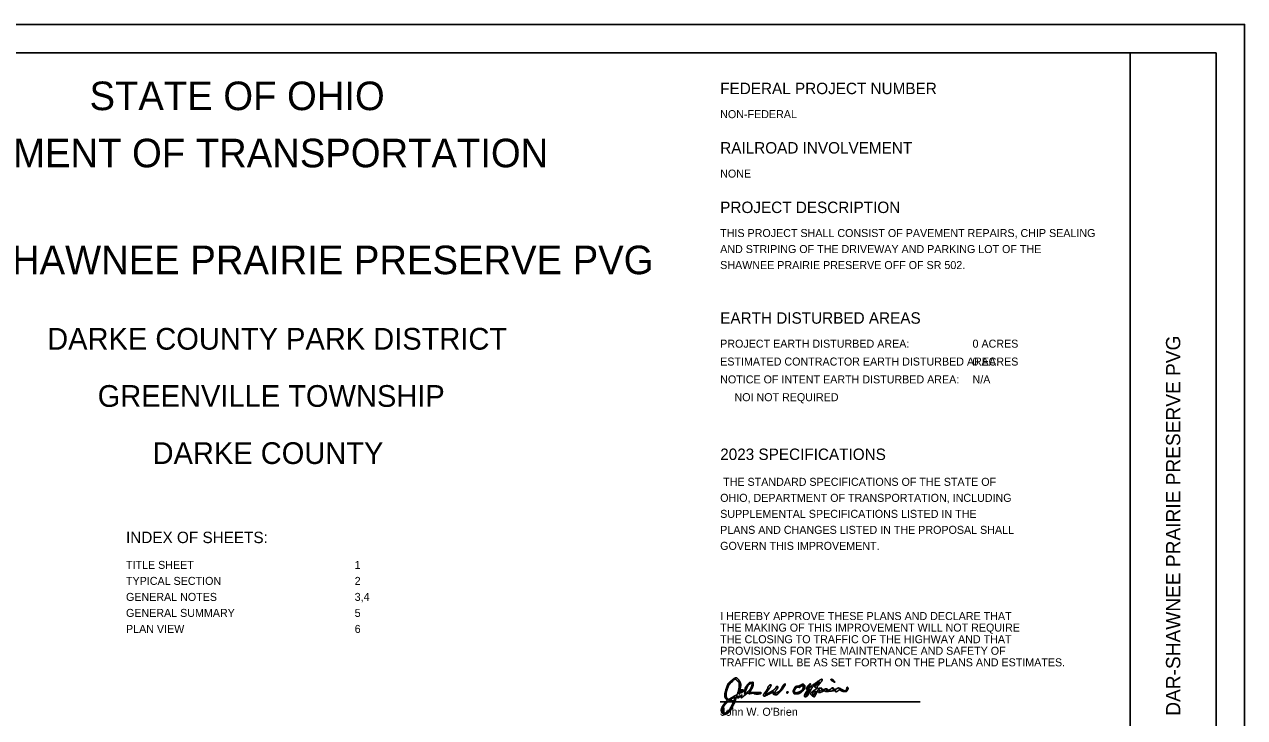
# Model space of a CAD drawing. Extents: x 0 to 68.9, y -26.1 to 22.
# Drawn here: x 12.66 to 34, y 9.87 to 22 of the extents above; entities that cross this region are included whole.
import ezdxf

# ---------------------------------------------------------------- set-up
doc = ezdxf.new("R2010")
doc.units = 0
for name, color, linetype in [('SH_Border', 7, 'Continuous'), ('SH_Cut_Line', 7, 'Continuous'), ('SH_Data', 7, 'Continuous'), ('SH_Text', 7, 'Continuous')]:
    doc.layers.add(name, color=color, linetype=linetype)

msp = doc.modelspace()

# ---------------------------------------------------------------- linework, layer by layer
at = {"layer": 'SH_Border'}
msp.add_line((32, 0.5), (32, 21.5), dxfattribs=at)
msp.add_lwpolyline([(1.5, 21.5), (33.5, 21.5), (33.5, 0.5), (1.5, 0.5)], close=True, dxfattribs=at)
at = {"layer": 'SH_Cut_Line'}
msp.add_lwpolyline([(0, 0), (34, 0), (34, 22), (0, 22)], close=True, dxfattribs=at)
at = {"layer": 'SH_Data'}
for p, q in [((24.827, 11.72), (24.827, 11.72)), ((24.827, 10.147), (28.327, 10.147))]:
    msp.add_line(p, q, dxfattribs=at)
at = {"layer": 'SH_Text'}
msp.add_line((26.792, 10.511), (26.792, 10.511), dxfattribs=at)
for points in [[(25.439, 10.315), (25.337, 10.315), (25.355, 10.339)], [(26.368, 10.336), (26.401, 10.369), (26.366, 10.314)], [(26.935, 10.375), (26.896, 10.392), (26.873, 10.383)], [(24.934, 10.196), (24.953, 10.175), (24.934, 10.154)]]:
    msp.add_lwpolyline(points, dxfattribs=at)
for points in [[(25.019, 10.518), (24.973, 10.477), (24.955, 10.448), (24.931, 10.374)], [(24.959, 10.395), (24.971, 10.429), (24.989, 10.457), (25.021, 10.489)], [(25.167, 10.509), (25.13, 10.57), (25.08, 10.573), (25.019, 10.518)], [(25.021, 10.489), (25.075, 10.545), (25.099, 10.549), (25.135, 10.51)], [(25.135, 10.51), (25.156, 10.489), (25.158, 10.48), (25.158, 10.436)], [(25.165, 10.344), (25.187, 10.408), (25.188, 10.475), (25.167, 10.509)], [(25.295, 10.396), (25.307, 10.429), (25.351, 10.471), (25.372, 10.471)], [(25.371, 10.49), (25.346, 10.489), (25.335, 10.484), (25.31, 10.455)], [(25.355, 10.339), (25.382, 10.375), (25.407, 10.439), (25.405, 10.467)], [(25.405, 10.467), (25.403, 10.49), (25.4, 10.491), (25.371, 10.49)], [(25.372, 10.471), (25.388, 10.471), (25.391, 10.469), (25.386, 10.453)], [(25.939, 10.448), (25.982, 10.483), (25.928, 10.377), (25.878, 10.327)], [(26.297, 10.444), (26.281, 10.459), (26.264, 10.458), (26.228, 10.439)], [(26.385, 10.454), (26.407, 10.473), (26.405, 10.451), (26.382, 10.416)], [(26.416, 10.366), (26.433, 10.399), (26.472, 10.437), (26.532, 10.478)], [(26.522, 10.497), (26.5, 10.481), (26.472, 10.46), (26.458, 10.452)], [(26.552, 10.449), (26.622, 10.524), (26.601, 10.557), (26.522, 10.497)], [(26.532, 10.478), (26.568, 10.503), (26.565, 10.487), (26.528, 10.455)], [(26.792, 10.511), (26.766, 10.527), (26.758, 10.544), (26.776, 10.543)], [(26.776, 10.543), (26.788, 10.543), (26.805, 10.53), (26.821, 10.509)], [(26.821, 10.509), (26.836, 10.491), (26.825, 10.492), (26.792, 10.511)], [(24.931, 10.374), (24.905, 10.295), (24.906, 10.225), (24.934, 10.196)], [(24.932, 10.246), (24.926, 10.275), (24.938, 10.338), (24.959, 10.395)], [(24.972, 10.191), (24.961, 10.191), (24.936, 10.226), (24.932, 10.246)], [(25.102, 10.263), (25.098, 10.263), (25.068, 10.247), (25.036, 10.227)], [(25.091, 10.163), (25.094, 10.192), (25.135, 10.281), (25.127, 10.221)], [(25.158, 10.436), (25.158, 10.376), (25.122, 10.263), (25.102, 10.263)], [(25.14, 10.234), (25.143, 10.238), (25.147, 10.242), (25.154, 10.247)], [(25.154, 10.289), (25.151, 10.292), (25.156, 10.317), (25.165, 10.344)], [(25.182, 10.329), (25.171, 10.296), (25.161, 10.282), (25.154, 10.289)], [(25.154, 10.247), (25.164, 10.258), (25.167, 10.247), (25.159, 10.239)], [(25.17, 10.239), (25.196, 10.266), (25.211, 10.271), (25.199, 10.248)], [(25.211, 10.359), (25.196, 10.359), (25.19, 10.353), (25.182, 10.329)], [(25.199, 10.248), (25.185, 10.222), (25.204, 10.22), (25.231, 10.243)], [(25.198, 10.319), (25.198, 10.323), (25.199, 10.329), (25.205, 10.343)], [(25.211, 10.323), (25.207, 10.306), (25.198, 10.307), (25.198, 10.319)], [(25.205, 10.343), (25.219, 10.35), (25.212, 10.331), (25.211, 10.323)], [(25.237, 10.342), (25.233, 10.353), (25.224, 10.359), (25.211, 10.359)], [(25.231, 10.243), (25.265, 10.272), (25.326, 10.316), (25.329, 10.29)], [(25.271, 10.398), (25.242, 10.32), (25.244, 10.324), (25.237, 10.342)], [(25.312, 10.327), (25.261, 10.282), (25.25, 10.285), (25.271, 10.337)], [(25.31, 10.455), (25.293, 10.435), (25.275, 10.41), (25.271, 10.398)], [(25.271, 10.337), (25.28, 10.36), (25.291, 10.387), (25.295, 10.396)], [(25.386, 10.453), (25.369, 10.397), (25.345, 10.356), (25.312, 10.327)], [(25.329, 10.29), (25.343, 10.292), (25.367, 10.296), (25.383, 10.299)], [(25.383, 10.299), (25.402, 10.303), (25.414, 10.302), (25.418, 10.296)], [(25.418, 10.296), (25.424, 10.287), (25.508, 10.284), (25.53, 10.292)], [(25.542, 10.306), (25.542, 10.313), (25.511, 10.315), (25.439, 10.315)], [(25.53, 10.292), (25.537, 10.295), (25.542, 10.301), (25.542, 10.306)], [(25.582, 10.266), (25.582, 10.272), (25.6, 10.301), (25.622, 10.331)], [(25.692, 10.291), (25.625, 10.255), (25.582, 10.245), (25.582, 10.266)], [(25.639, 10.313), (25.626, 10.295), (25.616, 10.279), (25.619, 10.279)], [(25.619, 10.279), (25.627, 10.279), (25.707, 10.322), (25.749, 10.348)], [(25.622, 10.331), (25.644, 10.361), (25.662, 10.39), (25.662, 10.395)], [(25.718, 10.44), (25.718, 10.432), (25.678, 10.367), (25.639, 10.313)], [(25.662, 10.395), (25.662, 10.41), (25.694, 10.447), (25.707, 10.447)], [(25.754, 10.308), (25.759, 10.327), (25.757, 10.327), (25.692, 10.291)], [(25.707, 10.447), (25.713, 10.447), (25.718, 10.444), (25.718, 10.44)], [(25.749, 10.348), (25.772, 10.363), (25.795, 10.384), (25.8, 10.395)], [(25.771, 10.279), (25.752, 10.286), (25.75, 10.291), (25.754, 10.308)], [(25.806, 10.351), (25.769, 10.301), (25.774, 10.286), (25.819, 10.31)], [(25.878, 10.327), (25.832, 10.281), (25.801, 10.267), (25.771, 10.279)], [(25.8, 10.395), (25.809, 10.416), (25.838, 10.423), (25.838, 10.405)], [(25.838, 10.405), (25.838, 10.399), (25.824, 10.375), (25.806, 10.351)], [(25.819, 10.31), (25.858, 10.33), (25.888, 10.361), (25.91, 10.405)], [(25.91, 10.405), (25.92, 10.423), (25.933, 10.443), (25.939, 10.448)], [(26.003, 10.327), (25.996, 10.327), (25.99, 10.322), (25.99, 10.315)], [(25.99, 10.315), (25.99, 10.301), (26.008, 10.303), (26.013, 10.318)], [(26.013, 10.318), (26.014, 10.323), (26.01, 10.327), (26.003, 10.327)], [(26.114, 10.367), (26.102, 10.341), (26.102, 10.332), (26.11, 10.312)], [(26.11, 10.312), (26.119, 10.29), (26.124, 10.287), (26.154, 10.287)], [(26.182, 10.423), (26.156, 10.423), (26.13, 10.402), (26.114, 10.367)], [(26.132, 10.317), (26.121, 10.328), (26.127, 10.355), (26.147, 10.381)], [(26.211, 10.324), (26.183, 10.311), (26.141, 10.307), (26.132, 10.317)], [(26.147, 10.381), (26.166, 10.406), (26.172, 10.409), (26.195, 10.405)], [(26.154, 10.287), (26.192, 10.287), (26.247, 10.314), (26.278, 10.347)], [(26.228, 10.439), (26.212, 10.43), (26.191, 10.423), (26.182, 10.423)], [(26.195, 10.405), (26.213, 10.402), (26.224, 10.404), (26.228, 10.411)], [(26.278, 10.409), (26.278, 10.379), (26.249, 10.342), (26.211, 10.324)], [(26.228, 10.411), (26.232, 10.417), (26.244, 10.424), (26.256, 10.428)], [(26.256, 10.428), (26.277, 10.433), (26.278, 10.431), (26.278, 10.409)], [(26.278, 10.347), (26.302, 10.372), (26.313, 10.428), (26.297, 10.444)], [(26.458, 10.452), (26.408, 10.42), (26.302, 10.288), (26.302, 10.258)], [(26.302, 10.258), (26.302, 10.245), (26.307, 10.239), (26.317, 10.239)], [(26.317, 10.239), (26.342, 10.239), (26.367, 10.272), (26.416, 10.366)], [(26.366, 10.314), (26.34, 10.27), (26.326, 10.256), (26.326, 10.273)], [(26.326, 10.273), (26.326, 10.28), (26.332, 10.29), (26.338, 10.295)], [(26.346, 10.367), (26.336, 10.367), (26.335, 10.372), (26.339, 10.385)], [(26.338, 10.295), (26.345, 10.301), (26.35, 10.31), (26.354, 10.315)], [(26.339, 10.385), (26.345, 10.406), (26.368, 10.44), (26.385, 10.454)], [(26.358, 10.374), (26.358, 10.37), (26.353, 10.367), (26.346, 10.367)], [(26.354, 10.315), (26.357, 10.322), (26.358, 10.331), (26.368, 10.336)], [(26.382, 10.416), (26.369, 10.397), (26.358, 10.378), (26.358, 10.374)], [(26.489, 10.362), (26.422, 10.321), (26.403, 10.278), (26.442, 10.252)], [(26.442, 10.252), (26.453, 10.245), (26.466, 10.239), (26.472, 10.239)], [(26.449, 10.276), (26.442, 10.294), (26.458, 10.324), (26.478, 10.329)], [(26.48, 10.292), (26.465, 10.261), (26.456, 10.257), (26.449, 10.276)], [(26.472, 10.239), (26.478, 10.239), (26.494, 10.266), (26.507, 10.297)], [(26.478, 10.329), (26.498, 10.335), (26.498, 10.328), (26.48, 10.292)], [(26.528, 10.455), (26.487, 10.419), (26.482, 10.409), (26.498, 10.391)], [(26.498, 10.391), (26.511, 10.377), (26.51, 10.376), (26.489, 10.362)], [(26.507, 10.297), (26.526, 10.341), (26.536, 10.356), (26.549, 10.358)], [(26.524, 10.398), (26.521, 10.41), (26.529, 10.424), (26.552, 10.449)], [(26.558, 10.386), (26.533, 10.382), (26.528, 10.384), (26.524, 10.398)], [(26.558, 10.331), (26.546, 10.323), (26.549, 10.311), (26.564, 10.311)], [(26.549, 10.358), (26.567, 10.361), (26.574, 10.341), (26.558, 10.331)], [(26.604, 10.364), (26.611, 10.382), (26.592, 10.392), (26.558, 10.386)], [(26.564, 10.311), (26.571, 10.311), (26.593, 10.319), (26.613, 10.329)], [(26.66, 10.372), (26.608, 10.351), (26.598, 10.349), (26.604, 10.364)], [(26.613, 10.329), (26.64, 10.342), (26.652, 10.344), (26.663, 10.337)], [(26.69, 10.358), (26.701, 10.376), (26.686, 10.382), (26.66, 10.372)], [(26.663, 10.337), (26.672, 10.331), (26.7, 10.331), (26.755, 10.336)], [(26.764, 10.377), (26.744, 10.359), (26.68, 10.343), (26.69, 10.358)], [(26.755, 10.336), (26.808, 10.341), (26.846, 10.36), (26.841, 10.335)], [(26.802, 10.375), (26.813, 10.392), (26.781, 10.393), (26.764, 10.377)], [(26.873, 10.383), (26.852, 10.367), (26.793, 10.361), (26.802, 10.375)], [(26.841, 10.335), (26.841, 10.322), (26.867, 10.326), (26.889, 10.344)], [(26.889, 10.344), (26.91, 10.36), (26.911, 10.36), (26.94, 10.346)], [(27.042, 10.386), (27.031, 10.344), (27, 10.34), (26.935, 10.375)], [(26.94, 10.346), (26.978, 10.328), (27.036, 10.327), (27.047, 10.343)], [(27.056, 10.401), (27.05, 10.407), (27.046, 10.403), (27.042, 10.386)], [(27.047, 10.343), (27.06, 10.364), (27.065, 10.392), (27.056, 10.401)], [(24.875, 10.083), (24.844, 10.037), (24.848, 9.956), (24.882, 9.933)], [(24.898, 9.951), (24.885, 9.951), (24.867, 10.01), (24.874, 10.035)], [(24.874, 10.035), (24.879, 10.058), (24.93, 10.126), (24.959, 10.149)], [(24.905, 10.124), (24.9, 10.119), (24.887, 10.101), (24.875, 10.083)], [(24.934, 10.154), (24.923, 10.142), (24.91, 10.128), (24.905, 10.124)], [(25.022, 10.071), (24.987, 10.005), (24.958, 9.97), (24.928, 9.958)], [(24.942, 9.943), (24.979, 9.962), (25.018, 10.009), (25.048, 10.074)], [(24.959, 10.149), (24.98, 10.166), (24.982, 10.167), (25.017, 10.154)], [(25.036, 10.227), (25.003, 10.207), (24.974, 10.191), (24.972, 10.191)], [(25.051, 10.168), (25.022, 10.17), (25.005, 10.176), (25.008, 10.185)], [(25.008, 10.185), (25.012, 10.195), (25.085, 10.235), (25.091, 10.23)], [(25.017, 10.154), (25.038, 10.147), (25.054, 10.14), (25.054, 10.138)], [(25.054, 10.138), (25.054, 10.136), (25.04, 10.105), (25.022, 10.071)], [(25.048, 10.074), (25.061, 10.101), (25.075, 10.128), (25.078, 10.135)], [(25.081, 10.196), (25.072, 10.176), (25.062, 10.168), (25.051, 10.168)], [(25.078, 10.135), (25.082, 10.14), (25.085, 10.15), (25.091, 10.163)], [(25.091, 10.23), (25.093, 10.227), (25.089, 10.212), (25.081, 10.196)], [(25.127, 10.221), (25.141, 10.216), (25.156, 10.224), (25.17, 10.239)], [(25.159, 10.239), (25.145, 10.228), (25.132, 10.223), (25.14, 10.234)], [(24.882, 9.933), (24.896, 9.924), (24.909, 9.926), (24.942, 9.943)], [(24.928, 9.958), (24.918, 9.954), (24.904, 9.951), (24.898, 9.951)]]:
    msp.add_open_spline(points, degree=2, dxfattribs=at)

# ---------------------------------------------------------------- texts
at = {"layer": 'SH_Data'}
msp.add_text('DAR-SHAWNEE PRAIRIE PRESERVE PVG', height=0.25, rotation=90, dxfattribs=at).set_placement((32.875, 9.906))
at = {"layer": 'SH_Text'}
for s, height, p in [('STATE OF OHIO', 0.5, (13.795, 20.5)), ('FEDERAL PROJECT NUMBER', 0.2, (24.827, 20.78)), ('NON-FEDERAL', 0.14, (24.827, 20.36)), ('DEPARTMENT OF TRANSPORTATION', 0.5, (9.747, 19.5)), ('RAILROAD INVOLVEMENT', 0.2, (24.827, 19.741)), ('NONE', 0.14, (24.827, 19.32)), ('PROJECT DESCRIPTION', 0.2, (24.827, 18.7)), ('THIS PROJECT SHALL CONSIST OF PAVEMENT REPAIRS, CHIP SEALING', 0.14, (24.827, 18.28)), ('AND STRIPING OF THE DRIVEWAY AND PARKING LOT OF THE', 0.14, (24.827, 18)), ('DAR SHAWNEE PRAIRIE PRESERVE PVG', 0.5, (10.395, 17.63)), ('SHAWNEE PRAIRIE PRESERVE OFF OF SR 502.', 0.14, (24.827, 17.72)), ('EARTH DISTURBED AREAS', 0.2, (24.827, 16.764)), ('DARKE COUNTY PARK DISTRICT', 0.38, (13.054, 16.31)), ('PROJECT EARTH DISTURBED AREA:', 0.14, (24.827, 16.345)), ('0 ACRES', 0.14, (29.241, 16.345)), ('ESTIMATED CONTRACTOR EARTH DISTURBED AREA:', 0.14, (24.827, 16.032)), ('0 ACRES', 0.14, (29.241, 16.032)), ('NOTICE OF INTENT EARTH DISTURBED AREA:', 0.14, (24.827, 15.72)), ('N/A', 0.14, (29.241, 15.72)), ('GREENVILLE TOWNSHIP', 0.38, (13.938, 15.31)), ('NOI NOT REQUIRED', 0.14, (25.077, 15.409)), ('DARKE COUNTY', 0.38, (14.898, 14.31)), ('2023 SPECIFICATIONS', 0.2, (24.827, 14.38)), (' THE STANDARD SPECIFICATIONS OF THE STATE OF', 0.14, (24.827, 13.928)), ('OHIO, DEPARTMENT OF TRANSPORTATION, INCLUDING', 0.14, (24.827, 13.648)), ('SUPPLEMENTAL SPECIFICATIONS LISTED IN THE', 0.14, (24.827, 13.368)), ('INDEX OF SHEETS:', 0.2, (14.433, 12.926)), ('PLANS AND CHANGES LISTED IN THE PROPOSAL SHALL', 0.14, (24.827, 13.088)), ('GOVERN THIS IMPROVEMENT.', 0.14, (24.827, 12.808)), ('TITLE SHEET', 0.14, (14.433, 12.475)), ('1', 0.14, (18.433, 12.475)), ('TYPICAL SECTION', 0.14, (14.433, 12.195)), ('2', 0.14, (18.433, 12.195)), ('GENERAL NOTES', 0.14, (14.433, 11.915)), ('3,4', 0.14, (18.433, 11.915)), ('GENERAL SUMMARY', 0.14, (14.433, 11.635)), ('5', 0.14, (18.433, 11.635)), ('I HEREBY APPROVE THESE PLANS AND DECLARE THAT', 0.14, (24.827, 11.58)), ('PLAN VIEW', 0.14, (14.433, 11.355)), ('6', 0.14, (18.433, 11.355)), ('THE MAKING OF THIS IMPROVEMENT WILL NOT REQUIRE', 0.14, (24.827, 11.378)), ('THE CLOSING TO TRAFFIC OF THE HIGHWAY AND THAT', 0.14, (24.827, 11.175)), ('PROVISIONS FOR THE MAINTENANCE AND SAFETY OF', 0.14, (24.827, 10.973)), ('TRAFFIC WILL BE AS SET FORTH ON THE PLANS AND ESTIMATES.', 0.14, (24.827, 10.77)), ("John W. O'Brien", 0.14, (24.827, 9.905))]:
    msp.add_text(s, height=height, dxfattribs=at).set_placement(p)

doc.saveas('drawing.dxf')
